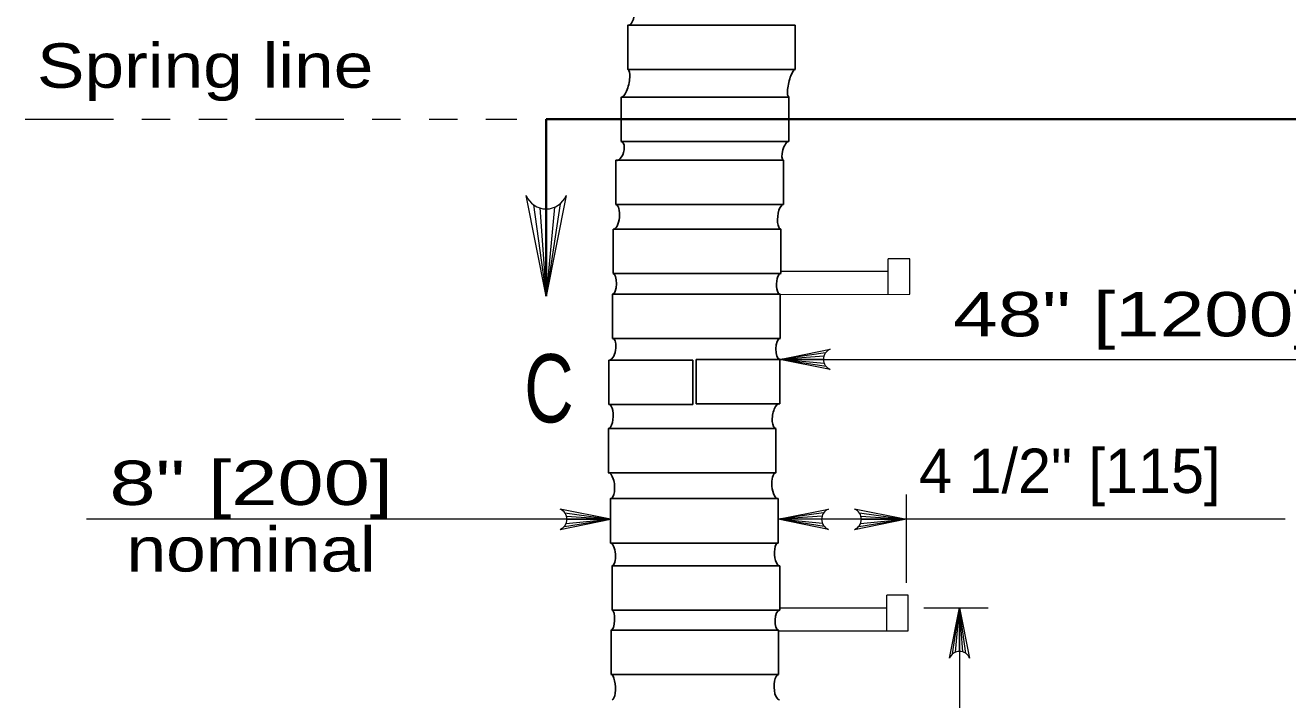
# Model space of a CAD drawing. Extents: x 1083.1 to 1117.1, y 697.4 to 741.4.
# Drawn here: x 1094.934 to 1099.373, y 732.34 to 734.711 of the extents above; entities that cross this region are included whole.
import ezdxf
from ezdxf.enums import TextEntityAlignment as Align

# ---------------------------------------------------------------- set-up
doc = ezdxf.new("R2010")
doc.units = 0
doc.header["$LTSCALE"] = 0.062
doc.linetypes.add('DASH_DOUBLE_DOT', pattern=[9.2, 5, -1.2, 0.3, -1.2, 0.3, -1.2])
doc.layers.add('1', color=7, linetype='Continuous', lineweight=13)

msp = doc.modelspace()

# ---------------------------------------------------------------- linework, layer by layer
at = {"layer": '1', "lineweight": 25}
for p, q in [((1097.64142, 734.555), (1097.64142, 734.71092)), ((1097.05217, 734.555), (1097.64142, 734.555)), ((1097.61867, 734.30258), (1097.61867, 734.45858)), ((1097.0295, 734.30258), (1097.61867, 734.30258)), ((1097.59975, 734.08033), (1097.59975, 734.23625)), ((1097.01058, 734.08033), (1097.59975, 734.08033)), ((1097.59033, 733.83792), (1097.59033, 733.99392)), ((1097.00108, 733.83792), (1097.59033, 733.83792)), ((1097.58842, 733.60958), (1097.58842, 733.76558)), ((1096.99917, 733.60958), (1097.58842, 733.60958)), ((1097.28092, 733.53383), (1096.98625, 733.53383)), ((1096.98625, 733.37783), (1096.98625, 733.53383)), ((1097.28092, 733.37783), (1097.28092, 733.53383)), ((1097.58742, 733.53633), (1097.29283, 733.53633)), ((1097.29283, 733.38042), (1097.29283, 733.53633)), ((1097.58742, 733.38042), (1097.58742, 733.53633)), ((1097.28092, 733.37792), (1096.98625, 733.37792)), ((1097.58742, 733.38042), (1097.29283, 733.38042)), ((1097.57333, 733.13692), (1097.57333, 733.29292)), ((1096.98408, 733.13692), (1097.57333, 733.13692)), ((1096.99167, 732.89058), (1096.99167, 733.04658)), ((1097.58083, 732.89058), (1097.58083, 733.04658)), ((1097.58083, 732.89058), (1097.58083, 733.04658)), ((1096.99167, 732.89058), (1097.58083, 732.89058)), ((1097.58658, 732.65425), (1097.58658, 732.81025)), ((1096.99733, 732.65425), (1097.58658, 732.65425)), ((1097.58275, 732.42792), (1097.58275, 732.58392)), ((1096.9935, 732.42792), (1097.58275, 732.42792))]:
    msp.add_line(p, q, dxfattribs=at)
at = {"layer": '1', "linetype": 'DASH_DOUBLE_DOT'}
msp.add_line((1094.93367, 734.38058), (1096.66258, 734.38058), dxfattribs=at)
at = {"layer": '1', "lineweight": 35}
for p, q in [((1096.7655, 734.38058), (1096.7655, 733.75883)), ((1097.61867, 734.38058), (1096.7655, 734.38058)), ((1097.61867, 734.38058), (1101.90767, 734.38058))]:
    msp.add_line(p, q, dxfattribs=at)
at = {"layer": '1'}
for p, q in [((1096.72067, 734.07933), (1096.7655, 733.75883)), ((1096.81508, 734.08308), (1096.7655, 733.75883)), ((1096.74283, 734.0685), (1096.7655, 733.75883)), ((1096.79433, 734.07083), (1096.7655, 733.75883)), ((1096.7655, 734.06517), (1096.7655, 733.75883)), ((1097.96825, 733.76492), (1097.96825, 733.89017)), ((1098.04383, 733.89017), (1097.96825, 733.89017)), ((1098.04383, 733.76492), (1098.04383, 733.89017)), ((1097.59033, 733.84625), (1097.96825, 733.84625)), ((1097.58842, 733.76483), (1098.04383, 733.76492)), ((1097.74767, 733.55875), (1097.58742, 733.53633)), ((1097.74225, 733.54767), (1097.58742, 733.53633)), ((1097.74058, 733.53633), (1097.58742, 733.53633)), ((1097.74342, 733.52192), (1097.58742, 733.53633)), ((1097.74958, 733.51158), (1097.58742, 733.53633)), ((1098.033, 732.75075), (1098.033, 733.06117)), ((1096.99167, 732.97383), (1095.1495, 732.97383)), ((1096.8295, 732.94908), (1096.99167, 732.97383)), ((1096.83142, 732.99625), (1096.99167, 732.97383)), ((1096.83567, 732.9595), (1096.99167, 732.97383)), ((1096.83683, 732.98517), (1096.99167, 732.97383)), ((1096.8385, 732.97383), (1096.99167, 732.97383)), ((1097.74108, 732.99625), (1097.58083, 732.97383)), ((1097.73567, 732.98517), (1097.58083, 732.97383)), ((1097.734, 732.97383), (1097.58083, 732.97383)), ((1097.73683, 732.9595), (1097.58083, 732.97383)), ((1097.743, 732.94908), (1097.58083, 732.97383)), ((1099.36417, 732.97383), (1097.58083, 732.97383)), ((1097.865, 732.94908), (1098.02717, 732.97383)), ((1097.86692, 732.99625), (1098.02717, 732.97383)), ((1097.87117, 732.9595), (1098.02717, 732.97383)), ((1097.87233, 732.98517), (1098.02717, 732.97383)), ((1097.874, 732.97383), (1098.02717, 732.97383)), ((1097.96317, 732.58133), (1097.96317, 732.70667)), ((1098.03875, 732.70667), (1097.96317, 732.70667)), ((1098.03875, 732.58133), (1098.03875, 732.70667)), ((1097.58658, 732.66267), (1097.96317, 732.66267)), ((1098.09358, 732.66267), (1098.31942, 732.66267)), ((1098.1945, 732.50058), (1098.21925, 732.66267)), ((1098.20483, 732.50667), (1098.21925, 732.66267)), ((1098.21925, 732.5095), (1098.21925, 732.66267)), ((1098.23058, 732.50792), (1098.21925, 732.66267)), ((1098.24167, 732.50242), (1098.21925, 732.66267)), ((1097.58275, 732.58133), (1098.03875, 732.58133))]:
    msp.add_line(p, q, dxfattribs=at)
at = {"layer": '1', "lineweight": 25}
for points in [[(1097.05217, 734.555), (1097.05217, 734.71092), (1097.64142, 734.71092)], [(1097.0295, 734.30258), (1097.0295, 734.45858), (1097.61867, 734.45858)], [(1097.01058, 734.08033), (1097.01058, 734.23625), (1097.59975, 734.23625)], [(1097.00108, 733.83792), (1097.00108, 733.99392), (1097.59033, 733.99392)], [(1096.99917, 733.60958), (1096.99917, 733.76558), (1097.58842, 733.76558)], [(1096.98408, 733.13692), (1096.98408, 733.29292), (1097.57333, 733.29292)], [(1096.99167, 732.89058), (1096.99167, 733.04658), (1097.58083, 733.04658)], [(1096.99167, 733.04658), (1097.03933, 733.04658), (1097.58083, 733.04658)], [(1096.99167, 732.89058), (1097.04683, 732.89058), (1097.58083, 732.89058)], [(1096.99733, 732.65425), (1096.99733, 732.81025), (1097.58658, 732.81025)], [(1096.9935, 732.42792), (1096.9935, 732.58392), (1097.58275, 732.58392)]]:
    msp.add_lwpolyline(points, dxfattribs=at)
at = {"layer": '1'}
for points in [[(1096.83633, 734.11283), (1096.7655, 733.75883), (1096.69475, 734.11283)], [(1097.76442, 733.50092), (1097.58742, 733.53633), (1097.76442, 733.57175)], [(1097.58842, 733.53633), (1100.79767, 733.53633), (1101.3495, 733.53633)], [(1096.81467, 732.9385), (1096.99167, 732.97383), (1096.81467, 733.00925)], [(1097.75783, 732.9385), (1097.58083, 732.97383), (1097.75783, 733.00925)], [(1097.85017, 732.9385), (1098.02717, 732.97383), (1097.85017, 733.00925)], [(1098.18383, 732.48567), (1098.21925, 732.66267), (1098.25467, 732.48567)], [(1098.21925, 732.66267), (1098.21925, 731.62708), (1098.21925, 731.182)]]:
    msp.add_lwpolyline(points, dxfattribs=at)
for centre, radius, start, end in [((1096.76544, 734.14143), 0.0764, 202.08782, 337.91395), ((1097.77872, 733.53639), 0.0382, 112.08782, 247.91395), ((1096.80034, 732.97391), 0.0382, 292.08605, 67.91218), ((1097.77216, 732.97391), 0.0382, 112.08782, 247.91395), ((1097.83587, 732.97391), 0.0382, 292.08605, 67.91218), ((1098.21929, 732.4714), 0.0382, 22.08782, 157.91395)]:
    msp.add_arc(centre, radius, start, end, dxfattribs=at)
at = {"layer": '1', "lineweight": 25}
for centre, major_axis, ratio, start_param, end_param in [((1097.05664, 734.74326), (0.00425, 0.03236), 0.53803, 3.1292062, 6.2707989), ((1097.04082, 734.50678), (0.01121, 0.04824), 0.311835, 3.1323355, 6.2739282), ((1097.63005, 734.50678), (0.01127, 0.04822), 0.238035, 6.2764231, 9.4180158), ((1097.02001, 734.26944), (0.00902, 0.03331), 0.545405, 3.1170644, 6.2586571), ((1097.60924, 734.26944), (-0.00933, -0.03322), 0.336345, 3.1296141, 6.2712067), ((1097.00582, 734.0371), (0.00463, 0.04321), 0.395652, 3.1354665, 6.2770591), ((1097.59506, 734.0371), (-0.00465, -0.0432), 0.355132, 3.1362853, 6.277878), ((1097.00014, 733.80176), (0.00093, 0.03619), 0.339333, 3.1403824, 6.281975), ((1097.58938, 733.80177), (-0.00093, -0.03619), 0.385436, 3.140164, 6.2817567), ((1096.99273, 733.57172), (0.00627, 0.03793), 0.451649, 3.1302607, 6.2718533), ((1097.58793, 733.57299), (-0.00049, -0.03664), 0.404629, 3.1407844, 6.282377), ((1096.98517, 733.33539), (0.00108, 0.04249), 0.377199, 3.1402157, 6.2818084), ((1097.58036, 733.33665), (-0.00687, -0.04379), 0.431696, 3.1315357, 6.2731284), ((1096.98785, 733.09174), (0.0037, -0.04521), 0.400858, 0.0047949, 3.1463876), ((1097.57708, 733.09174), (-0.0037, 0.04521), 0.39708, 0.0047328, 3.1463254), ((1096.99447, 732.8504), (0.00279, -0.04019), 0.361167, 0.0035249, 3.1451175), ((1097.58371, 732.8504), (-0.00278, 0.0402), 0.378539, 0.0037498, 3.1453425), ((1096.99542, 732.61906), (-0.00187, -0.03519), 0.307162, 6.280988, 9.4225806), ((1097.58465, 732.61907), (0.00185, 0.03519), 0.404304, 6.2800541, 9.4216467), ((1096.99541, 732.38373), (0.00187, -0.0442), 0.307813, 0.0017551, 3.1433478), ((1097.58465, 732.38373), (0.00185, -0.0442), 0.403909, 3.1440839, 6.2856766)]:
    msp.add_ellipse(centre, major_axis=major_axis, ratio=ratio, start_param=start_param, end_param=end_param, dxfattribs=at)

# ---------------------------------------------------------------- texts
at = {"layer": '1'}
for s, height, width, p in [('Spring line', 0.156, 1.2, (1094.97492, 734.49117)), ('48" [1200] diameter', 0.156, 1.35, (1098.19675, 733.61708)), ('C', 0.24, 0.75, (1096.68833, 733.31458))]:
    msp.add_text(s, height=height, dxfattribs=dict(at, width=width)).set_placement(p)
msp.add_text('4 1/2" [115]', height=0.156, dxfattribs=at).set_placement((1098.07675, 733.06633))
for s, width, p in [('8" [200]', 1.4, (1095.72812, 733.02425)), ('nominal', 1.2, (1095.72817, 732.79025))]:
    msp.add_text(s, height=0.156, dxfattribs=dict(at, width=width)).set_placement(p, align=Align.CENTER)

doc.saveas('drawing.dxf')
